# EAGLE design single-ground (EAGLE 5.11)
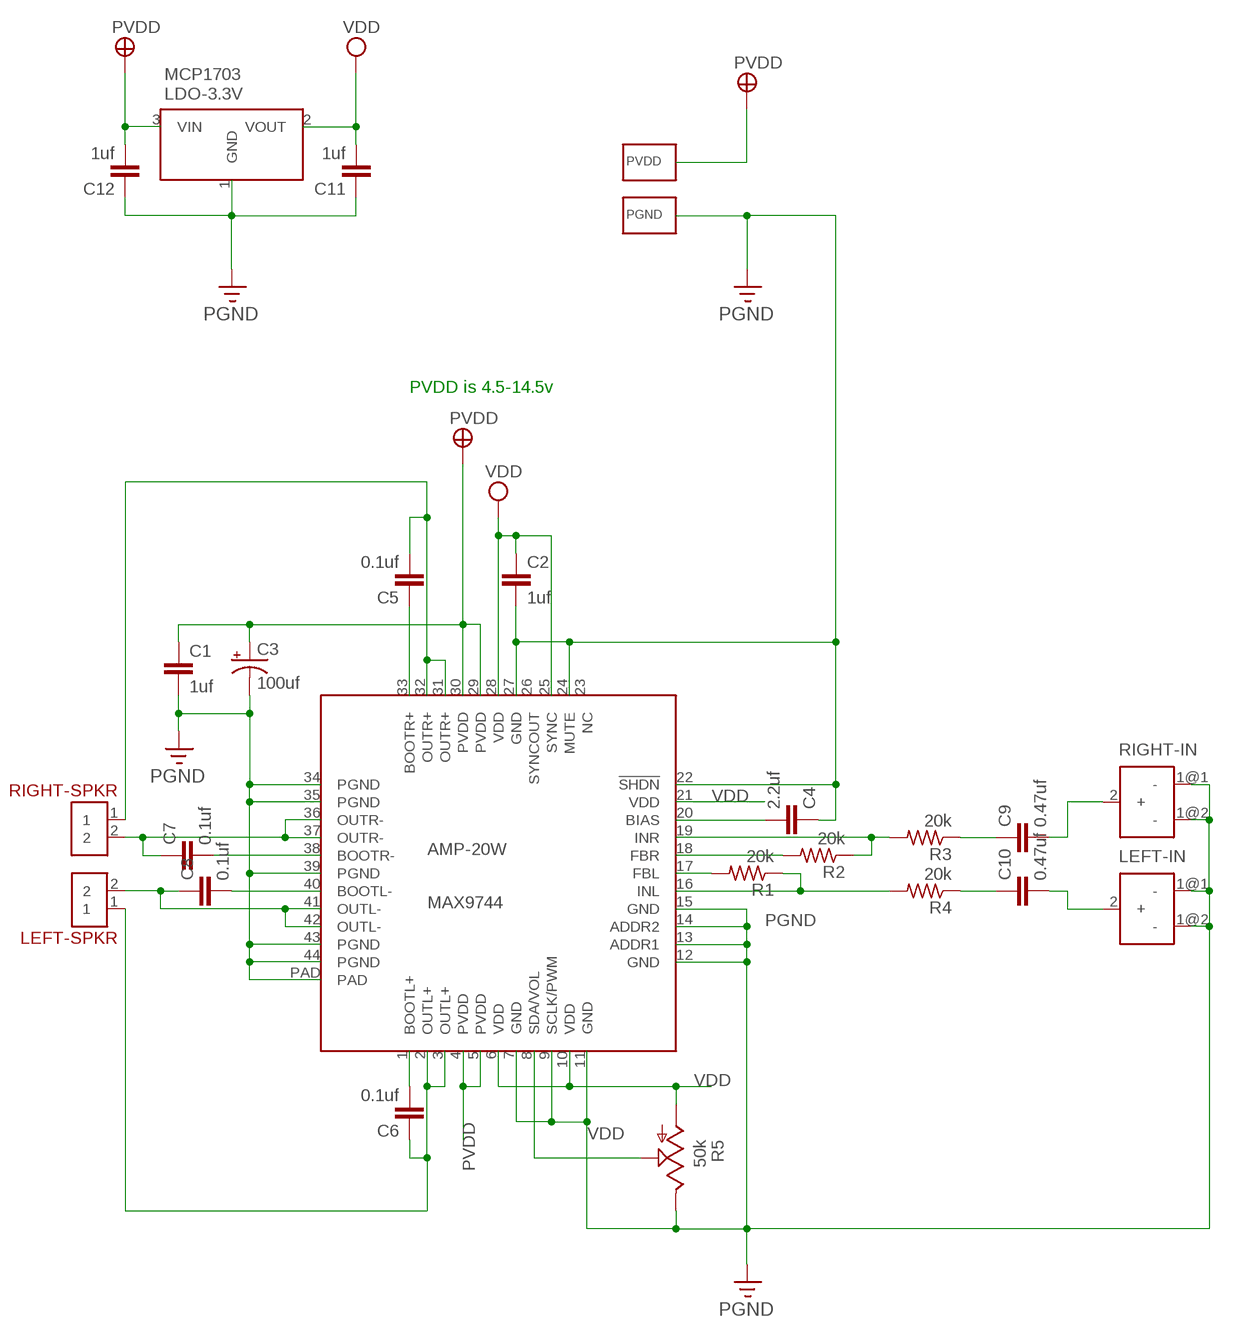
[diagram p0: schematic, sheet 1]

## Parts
AMP-20W  MAX9744  [QFN44-7X7-POWERPAD]
C1  1uf  C-EUC0805  [C0805]
C2  1uf  C-EUC0805  [C0805]
C3  100uf  CPOL-USE  [PANASONIC_E]
C4  2.2uf  C-EUC1206  [C1206]
C5  0.1uf  C-EUC0805  [C0805]
C6  0.1uf  C-EUC0805  [C0805]
C7  0.1uf  C-EUC0805  [C0805]
C8  0.1uf  C-EUC0805  [C0805]
C9  0.47uf  C-EUC1206  [C1206]
C10  0.47uf  C-EUC1206  [C1206]
C11  1uf  C-EUC0805  [C0805]
C12  1uf  C-EUC0805  [C0805]
LDO-3.3V  MCP1703  [SOT23-3]
LEFT-IN  AUDIO-JACK-MONO  [AUDIO-JACK-MONO-SMD]
LEFT-SPKR  SCREW-CLAMP-2X3.5MM  [SCREW-CLAMP-2X3.5MM]
PGND  WIREPAD-SMD-NO-VALUE5X5MM  [WIREPAD-SMD-5X5MM]
PVDD  WIREPAD-SMD-NO-VALUE5X5MM  [WIREPAD-SMD-5X5MM]
R1  20k  R-US_R0805  [R0805]
R2  20k  R-US_R0805  [R0805]
R3  20k  R-US_R0805  [R0805]
R4  20k  R-US_R0805  [R0805]
R5  50k  POT-TRIM-PARALLAX  [POT-TRIM-PARALLAX]
RIGHT-IN  AUDIO-JACK-MONO  [AUDIO-JACK-MONO-SMD]
RIGHT-SPKR  SCREW-CLAMP-2X3.5MM  [SCREW-CLAMP-2X3.5MM]

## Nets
N$1: AMP-20W.16(INL) R1.1 R4.2
N$2: AMP-20W.18(FBR) R2.2
N$3: AMP-20W.17(FBL) R1.2
N$4: AMP-20W.19(INR) R2.1 R3.2
N$5: AMP-20W.36(OUTR-) AMP-20W.37(OUTR-) C7.1 RIGHT-SPKR.2
N$6: C10.1 R4.1
N$7: AMP-20W.41(OUTL-) AMP-20W.42(OUTL-) C8.1 LEFT-SPKR.2
N$8: AMP-20W.40(BOOTL-) C8.2
N$9: AMP-20W.38(BOOTR-) C7.2
N$10: AMP-20W.2(OUTL+) AMP-20W.3(OUTL+) C6.1 LEFT-SPKR.1
N$11: AMP-20W.31(OUTR+) AMP-20W.32(OUTR+) C5.2 RIGHT-SPKR.1
N$12: AMP-20W.20(BIAS) C4.2
N$13: AMP-20W.1(BOOTL+) C6.2
N$14: AMP-20W.33(BOOTR+) C5.1
N$15: C9.1 R3.1
N$17: AMP-20W.8(SDA/VOL) R5.2(S)
N$19: C9.2 RIGHT-IN.2(+)
N$20: C10.2 LEFT-IN.2(+)
PGND: AMP-20W.7(GND) AMP-20W.9(SCLK/PWM) AMP-20W.11(GND) AMP-20W.12(GND) AMP-20W.13(ADDR1) AMP-20W.14(ADDR2) AMP-20W.15(GND) AMP-20W.22(!SHDN) AMP-20W.24(MUTE) AMP-20W.27(GND) AMP-20W.34(PGND) AMP-20W.35(PGND) AMP-20W.39(PGND) AMP-20W.43(PGND) AMP-20W.44(PGND) AMP-20W.PAD C1.2 C2.2 C3.- C4.1 C11.1 C12.1 LDO-3.3V.1(GND) LEFT-IN.1@1(-) LEFT-IN.1@2(-) PGND.1(P) R5.3(E) RIGHT-IN.1@1(-) RIGHT-IN.1@2(-)
PVDD: AMP-20W.4(PVDD) AMP-20W.5(PVDD) AMP-20W.29(PVDD) AMP-20W.30(PVDD) C1.1 C3.+ C12.2 LDO-3.3V.3(VIN) PVDD.1(P)
VDD: AMP-20W.6(VDD) AMP-20W.10(VDD) AMP-20W.21(VDD) AMP-20W.25(SYNC) AMP-20W.28(VDD) C2.1 C11.2 LDO-3.3V.2(VOUT) R5.1(A)
Unconnected: AMP-20W.23(NC) AMP-20W.26(SYNCOUT)

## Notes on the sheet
- PVDD is 4.5-14.5v

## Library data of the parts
AMP-20W = trl:MAX9744
C1 C2 C4-C12 = rcl:C-EU: CAPACITOR, European symbol
C3 = rcl:CPOL-US: POLARIZED CAPACITOR, American symbol
LDO-3.3V = trl:MCP1703
LEFT-IN RIGHT-IN = trl:AUDIO-JACK-MONO
LEFT-SPKR RIGHT-SPKR = trl:SCREW-CLAMP-2X3.5MM
PGND PVDD = trl:WIREPAD-SMD-NO-VALUE
R1-R4 = resistor:R-US_: RESISTOR, American symbol
R5 = trl:POT-TRIM-PARALLAX: POTENTIOMETER

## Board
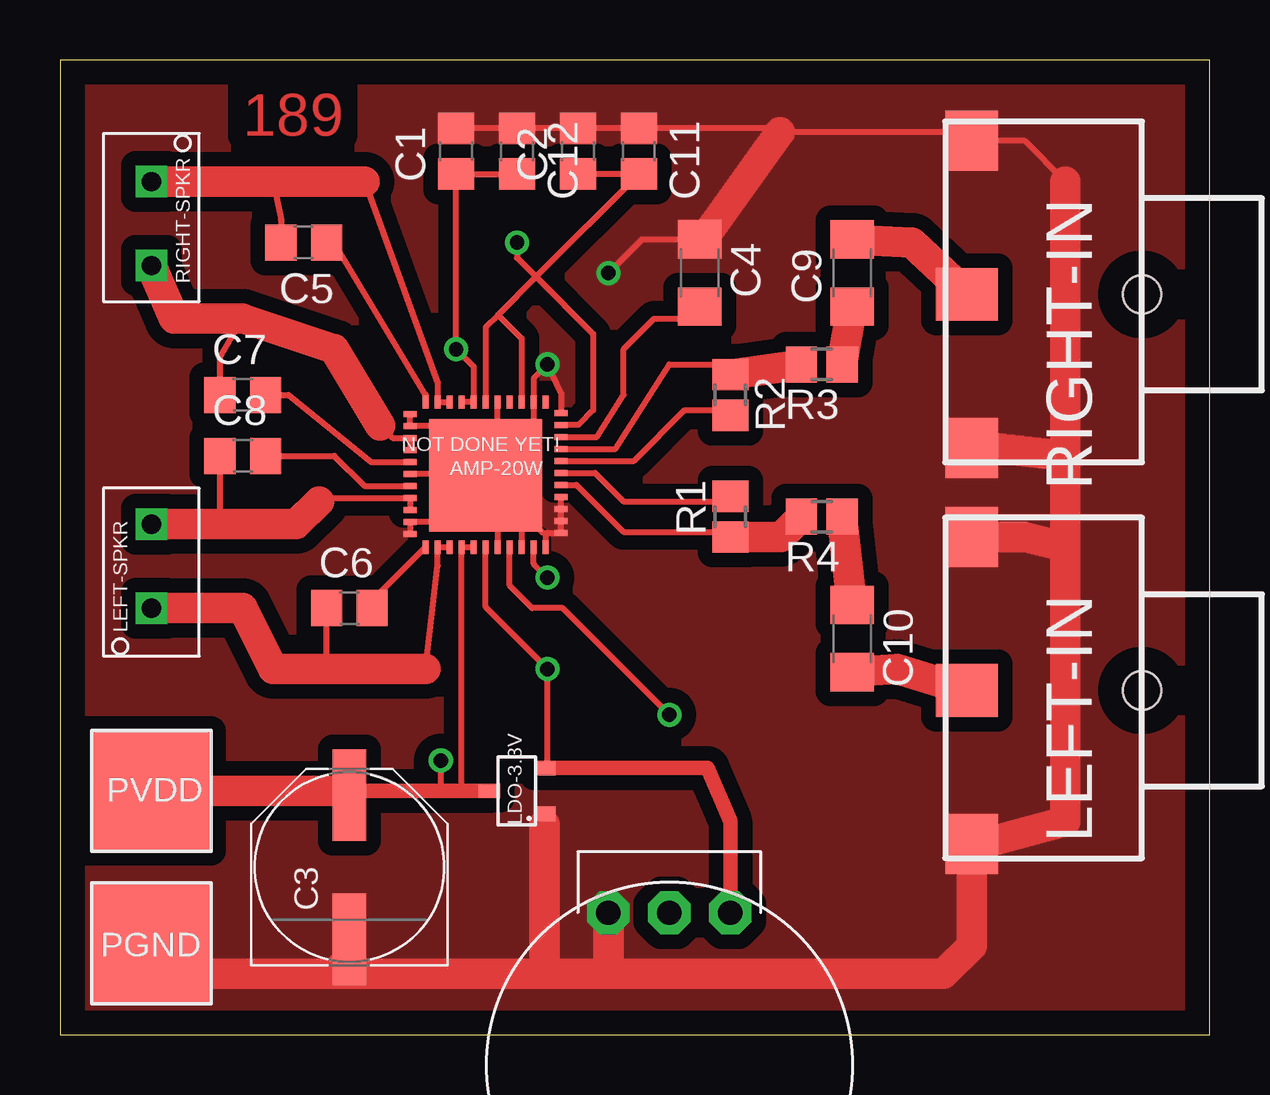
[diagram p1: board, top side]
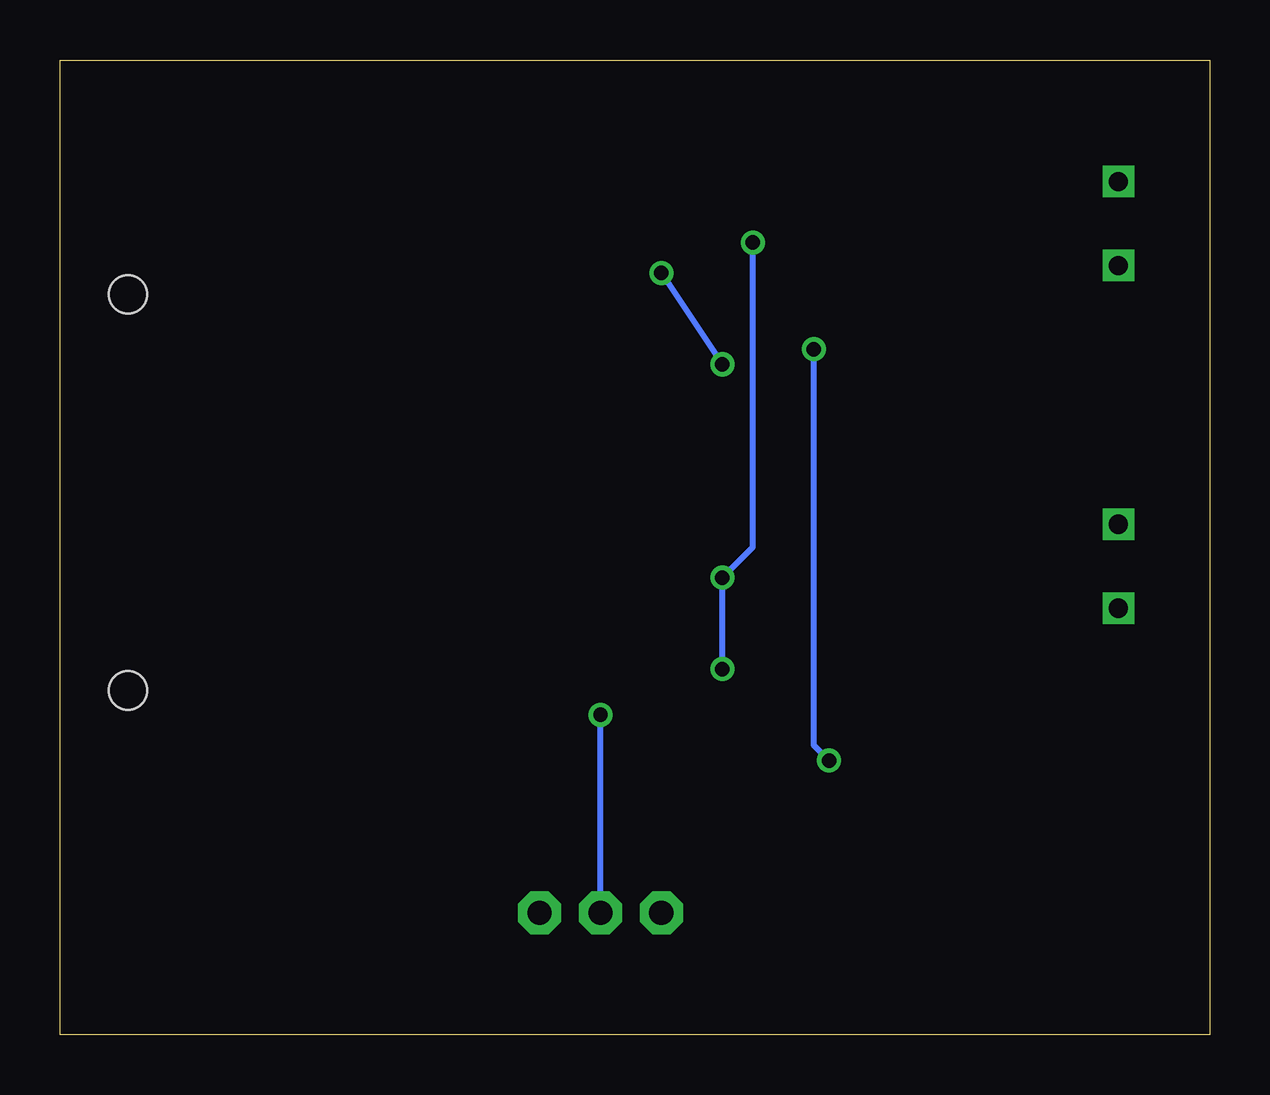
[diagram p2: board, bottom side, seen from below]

Size 47.93 x 40.63 mm. Coordinates in mm from the lower left corner, seen from the top.
Outline: 0,0 47.93,0 47.93,40.63 0,40.63 0,0
Copper layers (1*16): Top 0.035mm / dielectric 1.5mm / Bottom 0.035mm
Design rules "default": minimum track width 10mil, minimum drill 0.6mm, track to track 8mil, track to pad 8mil, pad to pad 8mil, via to via 8mil, smd to smd 8mil, copper to edge 40mil, drill to drill 8mil, minimum pad ring 10mil, minimum via ring 8mil, stop-mask expansion 4mil, vias tented up to drill 0mil, thermal gap 10mil

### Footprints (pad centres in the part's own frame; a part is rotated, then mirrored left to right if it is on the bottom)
QFN44-7X7-POWERPAD = smd 0.25 x 0.55: 1 0,0; 2 0.5,0; 3 1,0; 4 1.5,0; 5 2,0; 6 2.5,0; 7 3,0; 8 3.5,0; 9 4,0; 10 4.5,0; 11 5,0; 23 5,6.05; 24 4.5,6.05; 25 4,6.05; 26 3.5,6.05; 27 3,6.05; 28 2.5,6.05; 29 2,6.05; 30 1.5,6.05; 31 1,6.05; 32 0.5,6.05; 33 0,6.05 | smd 0.55 x 0.25: 12 5.65,0.6; 13 5.65,1.1; 14 5.65,1.6; 15 5.65,2.1; 16 5.65,2.6; 17 5.65,3.1; 18 5.65,3.6; 19 5.65,4.1; 20 5.65,4.6; 21 5.65,5.1; 22 5.65,5.6; 34 -0.65,5.55; 35 -0.65,5.05; 36 -0.65,4.55; 37 -0.65,4.05; 38 -0.65,3.55; 39 -0.65,3.05; 40 -0.65,2.55; 41 -0.65,2.05; 42 -0.65,1.55; 43 -0.65,1.05; 44 -0.65,0.55 | smd 4.7 x 4.7: PAD 2.5,3
C0805 = smd 1.3 x 1.5: 1 -0.95,0; 2 0.95,0
PANASONIC_E = smd 3.8 x 1.4: + 3,0; - -3,0
C1206 = smd 1.6 x 1.8: 1 -1.4,0; 2 1.4,0
SOT23-3 = smd 0.6 x 0.9: 1 -0.95,-1.15; 2 0.95,-1.15; 3 0,1.15
AUDIO-JACK-MONO-SMD = smd 2.2 x 2.5: 1@1 0.1,-14.4; 1@2 0.1,-1.6 | smd 2.6 x 2.2: 2 0.3,-8 | hole 1.6: -7,-8
SCREW-CLAMP-2X3.5MM = drill 0.8 square: 1 0,0; 2 3.5,0
WIREPAD-SMD-5X5MM = smd 5 x 5: 1 0,0
R0805 = smd 1.3 x 1.5: 1 -0.85,0; 2 0.85,0
POT-TRIM-PARALLAX = drill 1.016 pad 1.778 octagon: 1 -2.54,-3.81; 2 0,-3.81; 3 2.54,-3.81

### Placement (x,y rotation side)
AMP-20W  15.24,20.32 0 top
C1  16.51,36.83 90 top
C2  21.59,36.83 90 top
C3  12.06,6.99 90 top
C4  26.67,31.75 270 top
C5  10.16,33.02 180 top
C6  12.06,17.78 0 top
C7  7.62,26.67 0 top
C8  7.62,24.13 0 top
C9  33.02,31.75 90 top
C10  33.02,16.51 270 top
C11  24.13,36.83 270 top
C12  19.05,36.83 270 top
LDO-3.3V  19.05,10.16 90 top
LEFT-IN  38.1,6.35 180 top
LEFT-SPKR  3.81,17.78 90 top
PGND  3.81,3.81 270 top
PVDD  3.81,10.16 90 top
R1  27.94,21.59 90 top
R2  27.94,26.67 270 top
R3  31.75,27.94 180 top
R4  31.75,21.59 180 top
R5  25.4,1.27 180 top
RIGHT-IN  38.1,22.86 180 top
RIGHT-SPKR  3.81,35.56 270 top

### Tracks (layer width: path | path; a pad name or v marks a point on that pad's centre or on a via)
N$1
  Top 0.254: AMP-20W.16 21.53,22.92 23.5,20.95 27.73,20.95 R1.1
  Top 1.27: R1.1 30.05,20.74 R4.2
N$2
  Top 0.254: AMP-20W.18 23.92,23.92 26.04,26.04 27.73,26.04 R2.2
N$3
  Top 0.254: AMP-20W.17 22.3,23.42 23.5,22.23 27.73,22.23 R1.2
N$4
  Top 0.254: AMP-20W.19 23.15,24.42 25.4,27.94 27.52,27.94 R2.1
  Top 1.27: R2.1 R3.2
N$5
  Top 0.254: AMP-20W.37 AMP-20W.36 13.87,24.87 13.34,25.4 | C7.1 6.67,28.25 7.62,29.84
  Top 1.27: 13.34,25.4 11.43,28.57 7.62,29.84 4.75,29.84 RIGHT-SPKR.2
N$6
  Top 1.27: C10.1 R4.1
N$7
  Top 0.254: AMP-20W.42 AMP-20W.41 10.94,22.37 10.79,22.23 | C8.1 6.67,21.6 6.35,21.28
  Top 1.27: LEFT-SPKR.2 6.35,21.28 9.85,21.28 10.79,22.23
N$8
  Top 0.254: AMP-20W.40 12.69,22.87 11.43,24.13 C8.2
N$9
  Top 0.254: AMP-20W.38 12.96,23.87 9.53,26.67 C7.2
N$10
  Top 0.254: AMP-20W.3 AMP-20W.2 15.74,19.55 15.24,15.24 | 12.7,15.24 13.02,15.55 | C6.1 11.12,15.55 11.43,15.24
  Top 1.27: 15.24,15.24 12.7,15.24 11.43,15.24 8.89,15.24 7.62,17.78 LEFT-SPKR.1
N$11
  Top 0.254: AMP-20W.31 AMP-20W.32 15.74,27.17 12.7,35.56 | C5.2 9.21,33.97 8.89,35.56
  Top 1.27: RIGHT-SPKR.1 8.89,35.56 12.7,35.56
N$12
  Top 0.254: AMP-20W.20 22.38,24.92 23.5,26.67 23.5,28.57 24.77,29.84 26.16,29.84 C4.2
N$13
  Top 0.254: AMP-20W.1 12.7,17.78 C6.2
N$14
  Top 0.254: AMP-20W.33 15.24,26.67 11.43,33.02 C5.1
N$15
  Top 1.27: R3.1 C9.1
N$17  (via drill 0.6)
  Top 0.254: AMP-20W.8 18.74,18.73 19.68,17.78 20.95,17.78 v25.4,13.34
  Bottom 0.254: R5.2 v25.4,13.34
N$19
  Top 1.27: C9.2 35.52,33.02 RIGHT-IN.2
N$20
  Top 1.27: C10.2 34.88,15.24 LEFT-IN.2
PGND  (via drill 0.6)
  Top 0.254: AMP-20W.44 AMP-20W.43 15.79,21.37 AMP-20W.PAD | AMP-20W.7 18.24,22.82 AMP-20W.PAD | AMP-20W.9 19.24,21.82 AMP-20W.PAD | AMP-20W.15 AMP-20W.14 AMP-20W.13 AMP-20W.12 20.32,20.92 | 20.32,20.92 20.14,20.92 AMP-20W.PAD | AMP-20W.11 20.24,20.84 20.32,20.92 | AMP-20W.27 18.24,23.82 AMP-20W.PAD | AMP-20W.PAD 17.78,23.28 17.78,22.86 19.74,24.82 AMP-20W.24 19.74,27.36 v20.32,27.94 20.89,26.73 AMP-20W.22 | AMP-20W.39 17.69,23.37 AMP-20W.PAD | AMP-20W.34 AMP-20W.35 15.69,25.37 AMP-20W.PAD | C4.1 24.26,33.15 v22.86,31.75 | C1.2 C12.1 C2.2 C11.1 29.86,37.78 30.01,37.63 37.63,37.63 RIGHT-IN.1@1 40.21,37.26 41.91,35.56 | LEFT-IN.1@2 38.43,7.95
  Top 0.61: 20.2,8.77 LDO-3.3V.1
  Top 1.27: 38.43,7.95 41.91,8.89 41.91,20.32 | 41.91,20.32 41.91,24.13 | 41.91,24.13 41.91,35.56 | LEFT-IN.1@1 40.21,20.75 41.91,20.32 | RIGHT-IN.1@2 39.04,24.46 41.91,24.13 | LEFT-IN.1@2 38,3.71 36.83,2.54 22.86,2.54 | 11.43,2.54 5.08,2.54 PGND.1 | 11.43,2.54 20.32,2.54 | 20.32,2.54 22.86,2.54 | C3.- 12.06,3.17 11.43,2.54 | 22.86,2.54 R5.3 | 20.2,8.77 20.2,2.66 20.32,2.54 | C4.1 26.8,33.15 30.01,37.63
  Bottom 0.254: v22.86,31.75 v20.32,27.94
  pour Top (isolate 0.61, no thermals): 0,40.64 48.26,40.64 48.26,0 0,0
PVDD  (via drill 0.6)
  Top 0.254: AMP-20W.30 AMP-20W.29 17.24,27.84 v16.51,28.57 C1.1 C12.2 | AMP-20W.5 AMP-20W.4 16.74,10.39 16.51,10.16 | 15.88,10.16 v15.88,11.43
  Top 0.61: LDO-3.3V.3 16.51,10.16 15.88,10.16 12.24,10.16 C3.+
  Top 1.27: PVDD.1 11.89,10.16 C3.+
  Bottom 0.254: v16.51,28.57 16.51,12.06 v15.88,11.43
VDD  (via drill 0.6)
  Top 0.254: 20.38,10.94 LDO-3.3V.2 20.32,11.23 v20.32,15.24 17.74,17.82 AMP-20W.6 | AMP-20W.28 17.74,29.49 18.25,30 | 19.84,31.59 18.25,30 | 19.84,31.59 C11.2 C2.1 | AMP-20W.25 19.24,29.02 18.25,30 | AMP-20W.21 21.61,25.42 22.23,26.04 22.23,29.21 19.84,31.59 | v19.05,33.02 19.05,32.38 19.84,31.59 | AMP-20W.10 19.74,19.63 v20.32,19.05
  Top 0.61: LDO-3.3V.2 26.99,11.11 27.94,8.89 R5.1
  Bottom 0.254: v20.32,15.24 v20.32,19.05 19.05,20.32 v19.05,33.02

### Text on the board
Top: 189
